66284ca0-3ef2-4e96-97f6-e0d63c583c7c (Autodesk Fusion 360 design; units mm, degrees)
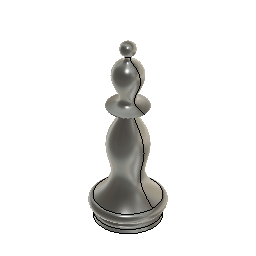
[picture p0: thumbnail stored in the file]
sketch "Sketch1" plane through (0, 0, 0) normal (0, 1, 0) x axis (1, 0, 0)
  line L1 (0, -60) -> (0, 0)
  line L2 (10, 0) -> (0, 0)
  line L3 (10, -1.5) -> (10, 0)
  curve K1 (10, -6.809) -> (1.2564, -55.5841)
  arc A1 centre (9.6718, -2.5205) radius 1.072 clockwise from (10, -3.5411) to (10, -1.5)
  arc A2 centre (9.7613, -5.175) radius 1.6513 clockwise from (10, -3.5411) to (10, -6.809)
  arc A3 centre (0.225, -57.6774) radius 2.3335 clockwise from (1.2564, -55.5841) to (0, -60)
  point P1 (0, 0)
  point P2 (0, 0)
  point P4 (0, 0)
  point P3 (0, -60)
  point P5 (10, 0)
  point P6 (10, -1.5)
  coincident P1 P2
  vertical L1
  coincident P1 P4
  perpendicular L1 L2
  perpendicular L2 L3
  dimension "d1" distance P2 P3 = 60
  dimension "d2" distance P4 P5 = 10
  dimension "d3" distance P5 P6 = 1.5
revolve "Revolve1" sketch "Sketch1" AlongAngle 360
